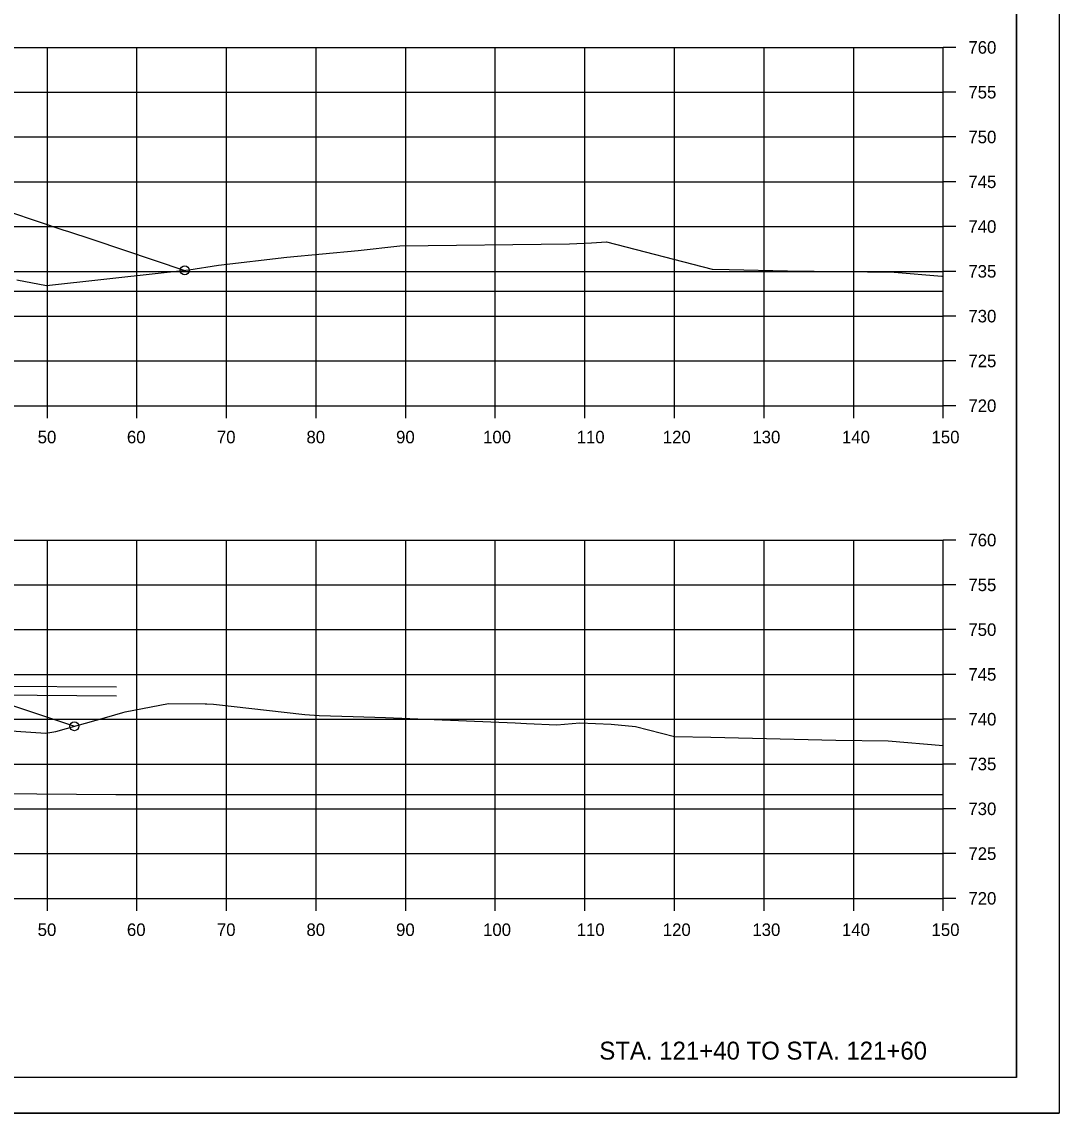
# Model space of a CAD drawing. Extents: x 1202951 to 1376887, y 378065 to 728038.
# Drawn here: x 1373144.3 to 1373260.1, y 380735.8 to 380857.6 of the extents above; entities that cross this region are included whole.
import ezdxf

# ---------------------------------------------------------------- set-up
doc = ezdxf.new("R2010")
doc.units = 0
for name, color, linetype in [('Default', 7, 'Continuous'), ('R_Axis', 7, 'Continuous'), ('R_Axis Annot', 7, 'Continuous'), ('R_Detour Annot', 7, 'Continuous'), ('R_Draft', 7, 'Continuous'), ('R_Exist Surface', 7, 'Continuous'), ('R_Grid', 7, 'Continuous'), ('R_No Plot', 7, 'Continuous')]:
    doc.layers.add(name, color=color, linetype=linetype)

msp = doc.modelspace()

# ---------------------------------------------------------------- linework, layer by layer
at = {"layer": 'Default'}
msp.add_line((1372947.13, 380827.54), (1373247.13, 380827.54), dxfattribs=at)
at = {"layer": 'R_Axis'}
for p, q in [((1373247.13, 380814.74), (1373247.13, 380854.74)), ((1373248.53, 380854.74), (1373247.13, 380854.74)), ((1373248.53, 380849.74), (1373247.13, 380849.74)), ((1373248.53, 380844.74), (1373247.13, 380844.74)), ((1373248.53, 380839.74), (1373247.13, 380839.74)), ((1373248.53, 380834.74), (1373247.13, 380834.74)), ((1373248.53, 380829.74), (1373247.13, 380829.74)), ((1373248.53, 380824.74), (1373247.13, 380824.74)), ((1373248.53, 380819.74), (1373247.13, 380819.74)), ((1372947.13, 380814.74), (1373247.13, 380814.74)), ((1373147.13, 380813.34), (1373147.13, 380814.74)), ((1373157.13, 380813.34), (1373157.13, 380814.74)), ((1373167.13, 380813.34), (1373167.13, 380814.74)), ((1373177.13, 380813.34), (1373177.13, 380814.74)), ((1373187.13, 380813.34), (1373187.13, 380814.74)), ((1373197.13, 380813.34), (1373197.13, 380814.74)), ((1373207.13, 380813.34), (1373207.13, 380814.74)), ((1373217.13, 380813.34), (1373217.13, 380814.74)), ((1373227.13, 380813.34), (1373227.13, 380814.74)), ((1373237.13, 380813.34), (1373237.13, 380814.74)), ((1373247.13, 380813.34), (1373247.13, 380814.74)), ((1373248.53, 380814.74), (1373247.13, 380814.74)), ((1373247.13, 380759.74), (1373247.13, 380799.74)), ((1373248.53, 380799.74), (1373247.13, 380799.74)), ((1373248.53, 380794.74), (1373247.13, 380794.74)), ((1373248.53, 380789.74), (1373247.13, 380789.74)), ((1373248.53, 380784.74), (1373247.13, 380784.74)), ((1373248.53, 380779.74), (1373247.13, 380779.74)), ((1373248.53, 380774.74), (1373247.13, 380774.74)), ((1373248.53, 380769.74), (1373247.13, 380769.74)), ((1373248.53, 380764.74), (1373247.13, 380764.74)), ((1372947.13, 380759.74), (1373247.13, 380759.74)), ((1373147.13, 380758.34), (1373147.13, 380759.74)), ((1373157.13, 380758.34), (1373157.13, 380759.74)), ((1373167.13, 380758.34), (1373167.13, 380759.74)), ((1373177.13, 380758.34), (1373177.13, 380759.74)), ((1373187.13, 380758.34), (1373187.13, 380759.74)), ((1373197.13, 380758.34), (1373197.13, 380759.74)), ((1373207.13, 380758.34), (1373207.13, 380759.74)), ((1373217.13, 380758.34), (1373217.13, 380759.74)), ((1373227.13, 380758.34), (1373227.13, 380759.74)), ((1373237.13, 380758.34), (1373237.13, 380759.74)), ((1373247.13, 380758.34), (1373247.13, 380759.74)), ((1373248.53, 380759.74), (1373247.13, 380759.74))]:
    msp.add_line(p, q, dxfattribs=at)
at = {"layer": 'R_Detour Annot'}
for p, q in [((1373005.08, 380784.54), (1373154.85, 380783.34)), ((1373005.07, 380783.54), (1373154.84, 380782.34)), ((1373004.99, 380772.54), (1373154.76, 380771.34)), ((1373154.76, 380771.34), (1373247.13, 380771.34))]:
    msp.add_line(p, q, dxfattribs=at)
at = {"layer": 'R_Exist Surface'}
for points in [[(1373026.75, 380828.17), (1373027.69, 380828.48), (1373057.38, 380838.38), (1373065.63, 380841.13), (1373070.63, 380841.03), (1373073.63, 380840.97), (1373074.12, 380840.97), (1373074.13, 380840.47), (1373075.13, 380840.49), (1373097.13, 380840.93), (1373119.13, 380840.49), (1373120.13, 380840.47), (1373120.14, 380840.97), (1373120.63, 380840.97), (1373123.63, 380841.03), (1373128.63, 380841.13), (1373134.47, 380839.19), (1373139.88, 380837.38), (1373148.98, 380834.35), (1373149.39, 380834.21), (1373152.19, 380833.28), (1373162.47, 380829.85)], [(1373143.72, 380828.8), (1373147.05, 380828.15), (1373159.85, 380829.58), (1373162.94, 380829.9), (1373166.24, 380830.43), (1373173.87, 380831.33), (1373181.83, 380832.06), (1373186.46, 380832.59), (1373205.4, 380832.82), (1373207.88, 380832.94), (1373209.53, 380833.02), (1373221.34, 380829.98), (1373223.24, 380829.94), (1373229.75, 380829.78), (1373241.66, 380829.65), (1373246.97, 380829.19), (1373247.13, 380829.19)], [(1373026.34, 380773.04), (1373065.63, 380786.13), (1373070.63, 380786.03), (1373073.63, 380785.97), (1373074.12, 380785.97), (1373074.13, 380785.47), (1373075.13, 380785.49), (1373097.13, 380785.93), (1373119.13, 380785.49), (1373120.13, 380785.47), (1373120.14, 380785.97), (1373120.63, 380785.97), (1373123.63, 380786.03), (1373128.63, 380786.13), (1373150.15, 380778.96)], [(1373140.82, 380778.59), (1373146.97, 380778.18), (1373148.07, 380778.38), (1373153.76, 380779.97), (1373155.56, 380780.5), (1373155.83, 380780.58), (1373160.64, 380781.5), (1373164.74, 380781.46), (1373164.92, 380781.47), (1373165.67, 380781.41), (1373175.87, 380780.25), (1373177.48, 380780.17), (1373181.26, 380780.05), (1373184.86, 380779.93), (1373199.36, 380779.33), (1373200.6, 380779.27), (1373204.01, 380779.13), (1373206.55, 380779.32), (1373210.05, 380779.18), (1373212.79, 380778.94), (1373217.12, 380777.82), (1373221.19, 380777.73), (1373235.14, 380777.39), (1373240.97, 380777.33), (1373247.13, 380776.79)]]:
    msp.add_lwpolyline(points, dxfattribs=at)
at = {"layer": 'R_Grid'}
for p, q in [((1372947.13, 380854.74), (1373247.13, 380854.74)), ((1373147.13, 380814.74), (1373147.13, 380854.74)), ((1373157.13, 380814.74), (1373157.13, 380854.74)), ((1373167.13, 380814.74), (1373167.13, 380854.74)), ((1373177.13, 380814.74), (1373177.13, 380854.74)), ((1373187.13, 380814.74), (1373187.13, 380854.74)), ((1373197.13, 380814.74), (1373197.13, 380854.74)), ((1373207.13, 380814.74), (1373207.13, 380854.74)), ((1373217.13, 380814.74), (1373217.13, 380854.74)), ((1373227.13, 380814.74), (1373227.13, 380854.74)), ((1373237.13, 380814.74), (1373237.13, 380854.74)), ((1373247.13, 380814.74), (1373247.13, 380854.74)), ((1372947.13, 380849.74), (1373247.13, 380849.74)), ((1372947.13, 380844.74), (1373247.13, 380844.74)), ((1372947.13, 380839.74), (1373247.13, 380839.74)), ((1372947.13, 380834.74), (1373247.13, 380834.74)), ((1372947.13, 380829.74), (1373247.13, 380829.74)), ((1372947.13, 380824.74), (1373247.13, 380824.74)), ((1372947.13, 380819.74), (1373247.13, 380819.74)), ((1372947.13, 380814.74), (1373247.13, 380814.74)), ((1372947.13, 380799.74), (1373247.13, 380799.74)), ((1373147.13, 380759.74), (1373147.13, 380799.74)), ((1373157.13, 380759.74), (1373157.13, 380799.74)), ((1373167.13, 380759.74), (1373167.13, 380799.74)), ((1373177.13, 380759.74), (1373177.13, 380799.74)), ((1373187.13, 380759.74), (1373187.13, 380799.74)), ((1373197.13, 380759.74), (1373197.13, 380799.74)), ((1373207.13, 380759.74), (1373207.13, 380799.74)), ((1373217.13, 380759.74), (1373217.13, 380799.74)), ((1373227.13, 380759.74), (1373227.13, 380799.74)), ((1373237.13, 380759.74), (1373237.13, 380799.74)), ((1373247.13, 380759.74), (1373247.13, 380799.74)), ((1372947.13, 380794.74), (1373247.13, 380794.74)), ((1372947.13, 380789.74), (1373247.13, 380789.74)), ((1372947.13, 380784.74), (1373247.13, 380784.74)), ((1372947.13, 380779.74), (1373247.13, 380779.74)), ((1372947.13, 380774.74), (1373247.13, 380774.74)), ((1372947.13, 380769.74), (1373247.13, 380769.74)), ((1372947.13, 380764.74), (1373247.13, 380764.74)), ((1372947.13, 380759.74), (1373247.13, 380759.74))]:
    msp.add_line(p, q, dxfattribs=at)
at = {"layer": 'R_No Plot'}
for p, q in [((1373255.31, 380739.74), (1373255.31, 380945.2)), ((1373255.31, 380739.74), (1372939.13, 380739.74)), ((1372926.73, 380735.76), (1373260.07, 380735.76))]:
    msp.add_line(p, q, dxfattribs=at)
for points in [[(1372926.73, 380949.1), (1373260.07, 380949.1), (1373260.07, 380735.76), (1372926.73, 380735.76)], [(1373173.05, 380945.2), (1373192.67, 380945.2), (1373192.67, 380935.32), (1373208.79, 380935.32), (1373231.99, 380935.32), (1373231.99, 380910.99), (1373255.31, 380910.99), (1373255.31, 380739.74), (1372939.13, 380739.74), (1372939.13, 380945.2)]]:
    msp.add_lwpolyline(points, close=True, dxfattribs=at)
for centre in [(1373162.47, 380829.85), (1373150.15, 380778.96)]:
    msp.add_circle(centre, 0.5, dxfattribs=at)

# ---------------------------------------------------------------- texts
at = {"layer": 'R_Axis Annot'}
for s, p in [('760', (1373249.93, 380854.04)), ('755', (1373249.93, 380849.04)), ('750', (1373249.93, 380844.04)), ('745', (1373249.93, 380839.04)), ('740', (1373249.93, 380834.04)), ('735', (1373249.93, 380829.04)), ('730', (1373249.93, 380824.04)), ('725', (1373249.93, 380819.04)), ('720', (1373249.93, 380814.04)), ('50', (1373146.05, 380810.54)), ('60', (1373156.01, 380810.54)), ('70', (1373166.05, 380810.54)), ('80', (1373176.05, 380810.54)), ('90', (1373186.05, 380810.54)), ('100', (1373195.76, 380810.54)), ('110', (1373206.21, 380810.54)), ('120', (1373215.82, 380810.54)), ('130', (1373225.82, 380810.54)), ('140', (1373235.82, 380810.54)), ('150', (1373245.82, 380810.54)), ('760', (1373249.93, 380799.04)), ('755', (1373249.93, 380794.04)), ('750', (1373249.93, 380789.04)), ('745', (1373249.93, 380784.04)), ('740', (1373249.93, 380779.04)), ('735', (1373249.93, 380774.04)), ('730', (1373249.93, 380769.04)), ('725', (1373249.93, 380764.04)), ('720', (1373249.93, 380759.04)), ('50', (1373146.05, 380755.54)), ('60', (1373156.01, 380755.54)), ('70', (1373166.05, 380755.54)), ('80', (1373176.05, 380755.54)), ('90', (1373186.05, 380755.54)), ('100', (1373195.76, 380755.54)), ('110', (1373206.21, 380755.54)), ('120', (1373215.82, 380755.54)), ('130', (1373225.82, 380755.54)), ('140', (1373235.82, 380755.54)), ('150', (1373245.82, 380755.54))]:
    msp.add_text(s, height=1.4, dxfattribs=at).set_placement(p)
at = {"layer": 'R_Draft'}
msp.add_text('STA. 121+40 TO STA. 121+60', height=2, dxfattribs=at).set_placement((1373208.74, 380741.74))

doc.saveas('drawing.dxf')
